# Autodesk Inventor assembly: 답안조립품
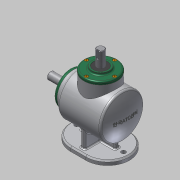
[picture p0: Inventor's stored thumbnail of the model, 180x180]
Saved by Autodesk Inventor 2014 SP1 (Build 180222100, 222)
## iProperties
Created: 2016-04
Part Number: 답안조립품
Document SubType Name: Assembly
Designer: SCD-A17
Author: SCD-A17
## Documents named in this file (14)
- C:\Users\SCD-A17\Desktop\460407V1015\답안조립품.iam
- C:\Users\SCD-A17\Desktop\460407V1015\본체.ipt
- C:\Users\SCD-A17\Desktop\460407V1015\서브 축.ipt
- 서브 축.ipt
- C:\Users\SCD-A17\Desktop\460407V1015\키 4x4.ipt
- C:\Users\SCD-A17\Desktop\460407V1015\메인 축.ipt
- 메인 축.ipt
- C:\Users\SCD-A17\Desktop\460407V1015\키 5x5.ipt
- C:\Users\SCD-A17\Desktop\460407V1015\메인 베벨기어.ipt
- C:\Users\SCD-A17\Desktop\460407V1015\서브 베벨기어.ipt
- C:\Users\SCD-A17\Desktop\460407V1015\베어링 6203.ipt
- C:\Users\SCD-A17\Desktop\460407V1015\커버.ipt
- C:\Users\SCD-A17\Desktop\460407V1015\오일실 17 32 8.ipt
- C:\Users\SCD-A17\Desktop\460407V1015\M4.ipt
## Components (8 placed, 1 different names)
1. M4:1
2. M4:3
3. M4:4
4. M4:5
5. M4:2
6. M4:6
7. M4:7
8. M4:8
